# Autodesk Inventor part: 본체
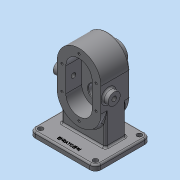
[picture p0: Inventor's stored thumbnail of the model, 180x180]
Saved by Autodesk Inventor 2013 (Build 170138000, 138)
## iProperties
Created: 2020-09
Part Number: 본체
Material: 일반
Document SubType Name: Modeling
Designer: Administrator
Density: 1 g/cm^3
Author: Administrator
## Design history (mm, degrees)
sketch "스케치1"
  geometry: L1 (-60, -50)-(60, -50); L2 (60, -50)-(60, 50); L3 (60, 50)-(-60, 50); L4 (-60, 50)-(-60, -50); L5 (-60, -50)-(60, 50); L6 (60, -50)-(-60, 50); 1 further point
  constraints: 12 end point, 2 midpoint, 2 parallel, 1 horizontal, 1 perpendicular
  dimensions: "d0" = 120 distance of L2.end L3.end; "d2" = 100 distance of L3.end L1.start
extrude "돌출1" new body sketch "스케치1" distance "d3" = 10; taper "d4" = 0 deg
fillet "모깎기1" dims "d5" = 10
sketch "스케치2"
  geometry: L1 (-40, -12)-(40, -12); L2 (40, -12)-(40, 25); L3 (40, 25)-(-40, 25); L4 (-40, 25)-(-40, -12); L5 (-40, -12)-(40, 25); L6 (40, -12)-(-40, 25); L7 (50, 50)-(-50, 50) reference; 3 further points
  constraints: 12 end point, 3 midpoint, 2 parallel, 1 horizontal, 1 perpendicular, 1 vertical alignment
  dimensions: "d6" = 80 distance of L1.start L1.end; "d8" = 37 distance of L1.end L2.end; "d9" = 25 distance between parallel lines of L7 L3
node "작업 평면1"
extrude "돌출2" join sketch "스케치2" distance "d11" = 142; taper "d12" = 0 deg
fillet "모깎기2" dims "d13" = 40
sketch "스케치3"
  geometry: L1 (16, 58)-(16, 102); L2 (64, 102)-(64, 58); L3 (-10, -10)-(90, -10) reference; A1 r 40 centre (40, 102) between (80, 102) and (0, 102) reference; A2 r 24 centre (40, 102) between (64, 102) and (16, 102); A3 r 24 centre (40, 58) between (16, 58) and (64, 58); 2 further points
  constraints: 4 end point, 4 point on circle, 4 tangent, 2 centre point, 2 vertical alignment, 1 concentric, 1 midpoint, 1 parallel, 1 vertical
  dimensions: "d14" = 24 radius of A2; "d16" = 44 distance of A3.centre A1.centre
extrude "돌출3" cut sketch "스케치3" distance "d17" = 21; taper "d18" = 0 deg
hole "구멍1" diameter "d21" = 17; stored, may be unused: countersink angle "d25" = 90 deg, drill point angle "d27" = 118 deg; dims "d19" = 10, "d20" = 10, "d22" = 6, "d23" = 4, "d24" = 2, "d26" = 8
hole "구멍2" diameter "d30" = 17; stored, may be unused: countersink angle "d34" = 90 deg, drill point angle "d36" = 118 deg; dims "d28" = 10, "d29" = 10, "d31" = 6, "d32" = 4, "d33" = 2, "d35" = 8
sketch "스케치4"
  geometry: L1 (80, 0)-(80, 102) reference; L2 (0, 0)-(0, 102) reference; L3 (80, 102)-(80, 58); L4 (0, 102)-(0, 58); L5 (64, 102)-(64, 58) reference; L6 (16, 58)-(16, 102) reference; A1 r 40 centre (40, 102) between (80, 102) and (0, 102) reference; A2 r 40 centre (40, 102) between (80, 102) and (0, 102); A3 r 40 centre (40, 58) between (0, 58) and (80, 58); A4 r 24 centre (40, 102) between (64, 102) and (16, 102) reference; A5 r 24 centre (40, 58) between (16, 58) and (64, 58) reference; 1 further point
  constraints: 6 tangent, 4 end point, 4 point on circle, 2 centre point, 2 point on line
  dimensions: "d37" = 44 distance of L1.end L3.end; "d38" = 44 distance of L2.end L4.end
extrude "돌출4" join sketch "스케치4" distance "d39" = 8; taper "d40" = 0 deg; dims "d41" = 45, "d42" = 0
sketch "스케치5"
  geometry: L1 (24, -44)-(24, 0) reference; L2 (-24, 0)-(-24, -44) reference; C1 r 8.5 at (0, 0) reference; C2 r 8.5 at (0, -44) reference; A1 r 24 centre (0, 0) between (24, 0) and (-24, 0) reference; A2 r 24 centre (0, -44) between (-24, -44) and (24, -44) reference; 1 further point
extrude "돌출5" join sketch "스케치5" distance "d43" = 8; taper "d44" = 0 deg
hole "구멍3" diameter "d47" = 25; stored, may be unused: countersink angle "d51" = 90 deg, drill point angle "d53" = 0 deg; dims "d45" = 10, "d46" = 10, "d48" = 6, "d49" = 4, "d50" = 2, "d52" = 15
sketch "스케치6"
  geometry: C1 r 8.5 at (40, -102) reference; C2 r 19 at (40, -102); 1 further point
  constraints: 1 centre point
  dimensions: "d63" = 38 diameter of C2
extrude "돌출6" join sketch "스케치6" distance "d65" = 17; taper "d66" = 0 deg
hole "구멍5" diameter "d69" = 28; stored, may be unused: countersink angle "d73" = 90 deg, drill point angle "d75" = 0 deg; dims "d67" = 10, "d68" = 10, "d70" = 6, "d71" = 4, "d72" = 2, "d74" = 7.3
hole "구멍6" diameter "d78" = 17; stored, may be unused: countersink angle "d82" = 90 deg, drill point angle "d84" = 0 deg; dims "d76" = 10, "d77" = 10, "d79" = 6, "d80" = 4, "d81" = 2, "d83" = 7.3
sketch "스케치7"
  geometry: C1 r 8.5 at (40, 58) reference; 1 further point
extrude "돌출7" join sketch "스케치7" stored distance "d85" = 17; taper "d86" = 0 deg
hole "구멍7" diameter "d89" = 25; stored, may be unused: countersink angle "d93" = 90 deg, drill point angle "d95" = 0 deg; dims "d87" = 10, "d88" = 10, "d90" = 6, "d91" = 4, "d92" = 2, "d94" = 15
sketch "스케치8"
  geometry: L1 (-10, 52)-(-10, -28) reference; L2 (58, 45)-(102, 45) reference; L3 (102, -8)-(58, -8) reference; C1 r 11 at (80, 6); 1 further point
  constraints: 1 centre point
  dimensions: "d96" = 90 distance from line of C1.centre L1; "d97" = 22 diameter of C1; "d181" = 14 distance from line of C1.centre L3
extrude "돌출8" join sketch "스케치8" distance "d99" = 10; taper "d100" = 0 deg
hole "구멍8" diameter "d103" = 8.376; stored, may be unused: countersink angle "d107" = 90 deg, drill point angle "d109" = 0 deg; dims "d101" = 10, "d102" = 10, "d104" = 6, "d105" = 4, "d106" = 2, "d108" = 15
sketch "스케치9"
  geometry: C1 r 12.5 at (40, 58) reference; A1 r 24 centre (40, 102) between (64, 102) and (16, 102) reference; 7 further points
  constraints: 3 horizontal alignment, 2 vertical alignment
  dimensions: "d110" = 31 distance of A1.centre point (40, 133); "d118" = 44 distance of point (71, 58) point (71, 102); "d119" = 31 distance of A1.centre point (71, 102); "d120" = 31 distance of A1.centre point (9, 102); "d121" = 31 distance of C1.centre point (9, 58); "d122" = 31 distance of point (40, 27) C1.centre; "d123" = 31 distance of point (71, 58) C1.centre
hole "구멍9" sketch "스케치9" diameter "d111" = 4.134; stored, may be unused: countersink angle "d115" = 90 deg, drill point angle "d117" = 118 deg; dims "d112" = 10, "d113" = 4, "d114" = 2, "d116" = 12
hole "구멍10" sketch "스케치9" diameter "d124" = 4.134; stored, may be unused: countersink angle "d128" = 90 deg, drill point angle "d130" = 118 deg; dims "d125" = 10, "d126" = 4, "d127" = 2, "d129" = 12
fillet "모깎기3" dims "d131" = 3
fillet "모깎기4" dims "d132" = 3
fillet "모깎기5" dims "d133" = 3
fillet "모깎기6" dims "d134" = 3
fillet "모깎기7" dims "d135" = 3
fillet "모깎기8" dims "d136" = 3
hole "구멍11" diameter "d139" = 9; stored, may be unused: countersink angle "d143" = 90 deg, drill point angle "d145" = 118 deg; dims "d137" = 10, "d138" = 10, "d140" = 9, "d141" = 4, "d142" = 2, "d144" = 12
hole "구멍12" diameter "d148" = 9; stored, may be unused: countersink angle "d152" = 90 deg, drill point angle "d154" = 118 deg; dims "d146" = 10, "d147" = 10, "d149" = 9, "d150" = 4, "d151" = 2, "d153" = 12
hole "구멍13" diameter "d157" = 9; stored, may be unused: countersink angle "d161" = 90 deg, drill point angle "d163" = 118 deg; dims "d155" = 10, "d156" = 10, "d158" = 9, "d159" = 4, "d160" = 2, "d162" = 12
hole "구멍14" diameter "d166" = 9; stored, may be unused: countersink angle "d170" = 90 deg, drill point angle "d172" = 118 deg; dims "d164" = 10, "d165" = 10, "d167" = 9, "d168" = 4, "d169" = 2, "d171" = 12
sketch "스케치10"
  geometry: L1 (-50, -50)-(50, -50) reference; L2 (-60, 40)-(-60, -40) reference; 2 further points
  constraints: 1 other
  dimensions: "d173" = 12 distance from line of L1 point (0, -38); "d174" = 60 distance from line of point (0, -38) L2
feature "엠보싱1" sketch "스케치10" dims "d2" = 100, "d175" = 0.5, "d176" = 0
fillet "모깎기9" dims "d177" = 3
chamfer "모따기1" distance "d178" = 1; stored, may be unused: second distance "d179" = 2, angle "d180" = 45 deg
fillet "모깎기10" dims "d182" = 0.5
chamfer "모따기2" distance "d183" = 0.7; stored, may be unused: second distance "d184" = 2, angle "d185" = 30 deg
node "솔리드1"
mirror "대칭1"
node "투영된 루프1"
